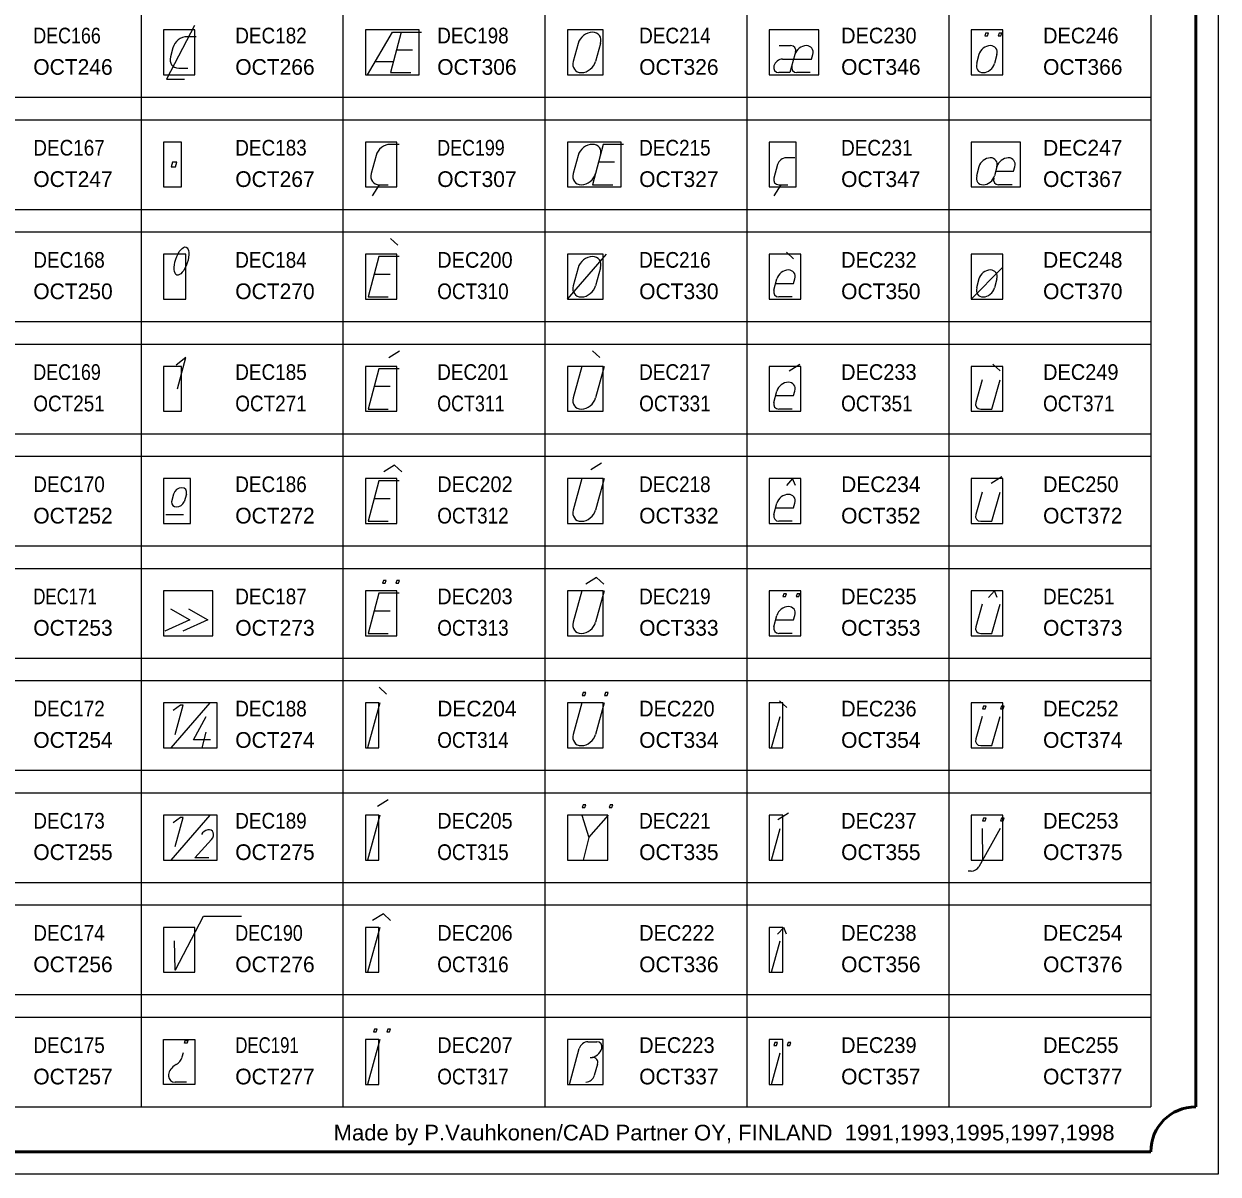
# Model space of a CAD drawing. Extents: x -200 to 7300, y -200 to 4800.
# Drawn here: x 4639 to 7300, y -200 to 2364 of the extents above; entities that cross this region are included whole.
import ezdxf
from ezdxf.enums import TextEntityAlignment as Align

# ---------------------------------------------------------------- set-up
doc = ezdxf.new("R2010")
doc.units = 0
doc.header["$LTSCALE"] = 14
for name, color, linetype, lineweight in [('1', 7, 'Continuous', 13), ('5', 7, 'Continuous', 40), ('6', 7, 'Continuous', 13), ('63', 7, 'Continuous', 13)]:
    doc.layers.add(name, color=color, linetype=linetype, lineweight=lineweight)
doc.layers.add('10', color=7, linetype='Continuous')
doc.layers.add('11', color=7, linetype='Continuous')

msp = doc.modelspace()

# ---------------------------------------------------------------- linework, layer by layer
at = {"layer": '1'}
for p, q in [((5023, 2335), (5003, 2335)), ((5874, 2320), (5863, 2280)), ((5924, 2320), (5913, 2280)), ((4971, 2310), (4966, 2290)), ((5505, 2305), (5470, 2305)), ((6322, 2315), (6347, 2315)), ((6767, 2295), (6762, 2275)), ((6807, 2295), (6802, 2275)), ((4983.9, 2265), (5004, 2265)), ((5422, 2280), (5463, 2280)), ((6391, 2255), (6361, 2255)), ((5475, 2095), (5455, 2095)), ((5424, 2070), (5413, 2030)), ((5874, 2070), (5863, 2030)), ((5955, 2055), (5920, 2055)), ((6318, 2050), (6310, 2020)), ((6357, 2065), (6337, 2065)), ((6767, 2045), (6762, 2025)), ((6807, 2045), (6802, 2025)), ((5431, 2005), (5415, 1980)), ((5431, 2005), (5451, 2005)), ((6326, 2005), (6310, 1980)), ((6321, 2005), (6341, 2005)), ((6841, 2005), (6811, 2005)), ((5472, 1870), (5456, 1885)), ((5850, 1750), (5937, 1850)), ((6354, 1840), (6338, 1855)), ((5874, 1820), (5863, 1780)), ((5924, 1820), (5913, 1780)), ((6819, 1820), (6750, 1750)), ((5455, 1805), (5420, 1805)), ((6310, 1770), (6317, 1795)), ((6767, 1795), (6762, 1775)), ((6807, 1795), (6802, 1775)), ((6351, 1755), (6321, 1755)), ((5452, 1620), (5476, 1635)), ((5922, 1620), (5906, 1635)), ((5882, 1600), (5863, 1530)), ((5932, 1600), (5913, 1530)), ((6344, 1590), (6368, 1605)), ((6814, 1590), (6798, 1605)), ((6774, 1570), (6760, 1520)), ((5455, 1555), (5420, 1555)), ((6310, 1520), (6317, 1545)), ((6351, 1505), (6321, 1505)), ((5902, 1370), (5926, 1385)), ((5882, 1350), (5863, 1280)), ((5932, 1350), (5913, 1280)), ((6794, 1340), (6818, 1355)), ((4972.5, 1315.4), (4968.2, 1298.2)), ((5001.1, 1315.4), (4996.3, 1298.5)), ((5455, 1305), (5420, 1305)), ((6774, 1320), (6760, 1270)), ((6310, 1270), (6317, 1295)), ((4955, 1270), (4995, 1270)), ((6351, 1255), (6321, 1255)), ((5882, 1100), (5863, 1030)), ((5932, 1100), (5913, 1030)), ((6774, 1070), (6760, 1020)), ((5455, 1055), (5420, 1055)), ((6310, 1020), (6317, 1045)), ((6351, 1005), (6321, 1005)), ((5447, 870), (5431, 885)), ((6339, 840), (6323, 855)), ((4967, 750), (5054, 850)), ((5432, 850), (5405, 750)), ((5882, 850), (5863, 780)), ((5932, 850), (5913, 780)), ((6305, 750), (6324, 820)), ((6774, 820), (6760, 770)), ((5036, 750), (5045, 785)), ((5427, 620), (5451, 635)), ((4967, 500), (5054, 600)), ((5432, 600), (5405, 500)), ((6319, 590), (6343, 605)), ((6305, 500), (6324, 570)), ((6814, 570), (6767, 485)), ((6774, 570), (6775, 500)), ((5898, 550), (5885, 500)), ((6750, 475), (6743, 475)), ((5432, 350), (5405, 250)), ((6305, 250), (6324, 320)), ((5432, 100), (5405, 0)), ((5855, 0), (5876.5, 80)), ((5895.5, 95), (5916, 95)), ((4994, 70), (4991, 61)), ((5901.1, 60), (5906.1, 60)), ((6305, 0), (6324, 70)), ((4978, 44), (4974, 41)), ((5917, 45), (5910, 20)), ((5001, 5), (4976, 5))]:
    msp.add_line(p, q, dxfattribs=at)
for points in [[(5019, 2360), (4957, 2240), (4997, 2240)], [(5405, 2250), (5460, 2345), (5525, 2345)], [(5480, 2345), (5456, 2255), (5501, 2255)], [(6357, 2295), (6346, 2255), (6321, 2255)], [(6329, 2285), (6394, 2285), (6397, 2295)], [(5975, 2095), (5930, 2095), (5906, 2005), (5951, 2005)], [(6804, 2035), (6844, 2035), (6847, 2045)], [(5475, 1845), (5430, 1845), (5406, 1755), (5451, 1755)], [(6314, 1785), (6354, 1785), (6357, 1795)], [(4981, 1550), (5000, 1620), (4978, 1603)], [(5475, 1595), (5430, 1595), (5406, 1505), (5451, 1505)], [(6771, 1505), (6796, 1505), (6814, 1570)], [(6314, 1535), (6354, 1535), (6357, 1545)], [(5481, 1365), (5465, 1380), (5441, 1365)], [(5475, 1345), (5430, 1345), (5406, 1255), (5451, 1255)], [(6358, 1335), (6352, 1350), (6338, 1335)], [(6771, 1255), (6796, 1255), (6814, 1320)], [(6314, 1285), (6354, 1285), (6357, 1295)], [(5931, 1115), (5915, 1130), (5891, 1115)], [(5475, 1095), (5430, 1095), (5406, 1005), (5451, 1005)], [(6808, 1085), (6802, 1100), (6788, 1085)], [(6771, 1005), (6796, 1005), (6814, 1070)], [(4966, 1060), (5009, 1035), (4953, 1010)], [(5006, 1060), (5049, 1035), (4993, 1010)], [(6314, 1035), (6354, 1035), (6357, 1045)], [(4976, 780), (4994, 845), (4988, 845), (4972, 833)], [(5055, 768), (5017, 768), (5045, 820)], [(6771, 755), (6796, 755), (6814, 820)], [(4976, 530), (4994, 595), (4988, 595), (4972, 583)], [(5882, 600), (5898, 550), (5942, 600)], [(5051, 505), (5020, 505), (5057, 546)], [(4974, 320), (4975, 255), (4977, 255), (5039, 375), (5124, 375)], [(5456, 365), (5440, 380), (5416, 365)], [(6338, 335), (6332, 350), (6318, 335)]]:
    msp.add_lwpolyline(points, dxfattribs=at)
for points in [[(6780, 2337), (6786, 2337), (6788, 2343), (6782, 2343)], [(6810, 2337), (6816, 2337), (6818, 2343), (6812, 2343)], [(4967, 2045), (4977, 2045), (4980, 2055), (4970, 2055)], [(5438, 1117), (5444, 1117), (5446, 1123), (5440, 1123)], [(5468, 1117), (5474, 1117), (5476, 1123), (5470, 1123)], [(6330, 1087), (6336, 1087), (6338, 1093), (6332, 1093)], [(6360, 1087), (6366, 1087), (6368, 1093), (6362, 1093)], [(5883, 867), (5889, 867), (5891, 873), (5885, 873)], [(5933, 867), (5939, 867), (5941, 873), (5935, 873)], [(6775, 837), (6781, 837), (6783, 843), (6777, 843)], [(6815, 837), (6821, 837), (6823, 843), (6817, 843)], [(5883, 617), (5889, 617), (5891, 623), (5885, 623)], [(5943, 617), (5949, 617), (5951, 623), (5945, 623)], [(6775, 587), (6781, 587), (6783, 593), (6777, 593)], [(6815, 587), (6821, 587), (6823, 593), (6817, 593)], [(5418, 117), (5424, 117), (5426, 123), (5420, 123)], [(5448, 117), (5454, 117), (5456, 123), (5450, 123)], [(5003, 92), (4997, 92), (4998, 98), (5004, 98)], [(6310, 87), (6316, 87), (6318, 93), (6312, 93)], [(6340, 87), (6346, 87), (6348, 93), (6342, 93)]]:
    msp.add_lwpolyline(points, close=True, dxfattribs=at)
for centre, major_axis, start_param, end_param in [((5899, 2320), (-21.5, -18.81), 2.2896326, 5.4312252), ((4995.99, 2310), (-21.5, -18.81), 3.860429, 5.4312252), ((4990.63, 2290), (21.5, 18.81), 2.2896328, 3.860429), ((6343.32, 2300), (-12.9, -11.29), 2.2896327, 3.860429), ((6376.98, 2295), (-17.2, -15.05), 2.2896326, 5.4312252), ((6787, 2295), (-17.2, -15.05), 2.2896326, 5.4312252), ((5888, 2280), (21.5, 18.81), 2.2896328, 5.4312254), ((6325.28, 2270), (-12.9, -11.29), 3.860429, 7.0020216), ((6365.29, 2270), (12.9, 11.29), 2.2896328, 3.860429), ((6782, 2275), (17.2, 15.05), 2.2896328, 5.4312254), ((5448.69, 2070), (-21.5, -18.81), 3.860429, 5.4312252), ((5899, 2070), (-21.5, -18.81), 2.2896326, 5.4312252), ((6333.34, 2050), (-12.9, -11.29), 3.860429, 5.4312252), ((6787, 2045), (-17.2, -15.05), 2.2896326, 5.4312252), ((6827, 2045), (-17.2, -15.05), 2.2896326, 5.4312252), ((5437.97, 2030), (21.5, 18.81), 2.2896328, 3.860429), ((5888, 2030), (21.5, 18.81), 2.2896328, 5.4312254), ((6782, 2025), (17.2, 15.05), 2.2896328, 5.4312254), ((6325.3, 2020), (12.9, 11.29), 2.2896328, 3.860429), ((6815.02, 2020), (12.9, 11.29), 2.2896328, 3.860429), ((5899, 1820), (-21.5, -18.81), 2.2896326, 5.4312252), ((6337.02, 1795), (-17.2, -15.05), 2.2896326, 5.4312252), ((6787, 1795), (-17.2, -15.05), 2.2896326, 5.4312252), ((5888, 1780), (21.5, 18.81), 2.2896328, 5.4312254), ((6325.32, 1770), (12.9, 11.29), 2.2896328, 3.860429), ((6782, 1775), (17.2, 15.05), 2.2896328, 5.4312254), ((6337.03, 1545), (-17.2, -15.05), 2.2896326, 5.4312252), ((5888, 1530), (21.5, 18.81), 2.2896328, 5.4312254), ((6325.33, 1520), (12.9, 11.29), 2.2896328, 3.860429), ((6775, 1520), (12.9, 11.29), 2.2896328, 3.860429), ((4986.79, 1315.43), (-12.29, -10.75), 2.2896326, 5.4312252), ((6337.05, 1295), (-17.2, -15.05), 2.2896326, 5.4312252), ((4982.96, 1301.14), (12.29, 10.75), 2.4993147, 5.2422622), ((5888, 1280), (21.5, 18.81), 2.2896328, 5.4312254), ((6325.35, 1270), (12.9, 11.29), 2.2896328, 3.860429), ((6775, 1270), (12.9, 11.29), 2.2896328, 3.860429), ((6337.06, 1045), (-17.2, -15.05), 2.2896326, 5.4312252), ((5888, 1030), (21.5, 18.81), 2.2896328, 5.4312254), ((6325.36, 1020), (12.9, 11.29), 2.2896328, 3.860429), ((6775, 1020), (12.9, 11.29), 2.2896328, 3.860429), ((5888, 780), (21.5, 18.81), 2.2896328, 5.4312254), ((6775, 770), (12.9, 11.29), 2.2896328, 3.860429), ((5047.28, 553.61), (-12.04, -10.54), 1.7153279, 5.1862467), ((6754.5, 490.48), (12.9, 11.29), 3.8604291, 5.0573215), ((5891.5, 80), (-12.9, -11.29), 3.860429, 5.4312252), ((5906.5, 80), (17.2, 15.05), 3.860429, 5.4312252), ((5911.5, 80), (-12.9, -11.29), 2.2896326, 3.8604289), ((4971.32, 60.7), (17.2, 15.05), 4.4484316, 5.4312253), ((5902.12, 45), (-12.9, -11.29), 2.2896326, 3.8642293), ((4981.75, 25), (17.2, 15.05), 1.3623375, 3.860429), ((5895.42, 20), (-12.9, -11.29), 0.7188363, 2.2896326)]:
    msp.add_ellipse(centre, major_axis=major_axis, ratio=0.765566, start_param=start_param, end_param=end_param, dxfattribs=at)
msp.add_ellipse((4990.22, 1835), major_axis=(10.22, 31.22), ratio=0.408607, dxfattribs=at)
at = {"layer": '5', "lineweight": 53}
for p, q in [((7250, 4650), (7250, -50)), ((7150, -150), (-50, -150))]:
    msp.add_line(p, q, dxfattribs=at)
at = {"layer": '5', "lineweight": 25}
msp.add_lwpolyline([(-200, -200), (-200, 4800), (7300, 4800), (7300, -200)], close=True, dxfattribs=at)
at = {"layer": '5', "lineweight": 53}
msp.add_arc((7250, -150), 100, 90, 179.99999, dxfattribs=at)
at = {"layer": '6'}
for p, q in [((4900, 3950), (4900, -50)), ((5350, 3950), (5350, -50)), ((5800, 3950), (5800, -50)), ((6250, 3950), (6250, -50)), ((6700, 3950), (6700, -50)), ((7150, 3950), (7150, -50)), ((-50, 2200), (7150, 2200)), ((-50, 2150), (7150, 2150)), ((-50, 1950), (7150, 1950)), ((-50, 1900), (7150, 1900)), ((-50, 1700), (7150, 1700)), ((-50, 1650), (7150, 1650)), ((-50, 1450), (7150, 1450)), ((-50, 1400), (7150, 1400)), ((-50, 1200), (7150, 1200)), ((-50, 1150), (7150, 1150)), ((-50, 950), (7150, 950)), ((-50, 900), (7150, 900)), ((-50, 700), (7150, 700)), ((-50, 650), (7150, 650)), ((-50, 450), (7150, 450)), ((-50, 400), (7150, 400)), ((-50, 200), (7150, 200)), ((-50, 150), (7150, 150)), ((-50, -50), (7150, -50))]:
    msp.add_line(p, q, dxfattribs=at)
at = {"layer": '63'}
for points in [[(4950, 2250), (5020, 2250), (5020, 2350), (4950, 2350)], [(5400, 2250), (5520, 2250), (5520, 2350), (5400, 2350)], [(5850, 2250), (5930, 2250), (5930, 2350), (5850, 2350)], [(6300, 2250), (6410, 2250), (6410, 2350), (6300, 2350)], [(6750, 2250), (6820, 2250), (6820, 2350), (6750, 2350)], [(4950, 2000), (4990, 2000), (4990, 2100), (4950, 2100)], [(5400, 2000), (5470, 2000), (5470, 2100), (5400, 2100)], [(5850, 2000), (5970, 2000), (5970, 2100), (5850, 2100)], [(6300, 2000), (6360, 2000), (6360, 2100), (6300, 2100)], [(6750, 2000), (6860, 2000), (6860, 2100), (6750, 2100)], [(4950, 1750), (5000, 1750), (5000, 1850), (4950, 1850)], [(5400, 1750), (5470, 1750), (5470, 1850), (5400, 1850)], [(5850, 1750), (5930, 1750), (5930, 1850), (5850, 1850)], [(6300, 1750), (6370, 1750), (6370, 1850), (6300, 1850)], [(6750, 1750), (6820, 1750), (6820, 1850), (6750, 1850)], [(4950, 1500), (4990, 1500), (4990, 1600), (4950, 1600)], [(5400, 1500), (5470, 1500), (5470, 1600), (5400, 1600)], [(5850, 1500), (5930, 1500), (5930, 1600), (5850, 1600)], [(6300, 1500), (6370, 1500), (6370, 1600), (6300, 1600)], [(6750, 1500), (6820, 1500), (6820, 1600), (6750, 1600)], [(4950, 1250), (5010, 1250), (5010, 1350), (4950, 1350)], [(5400, 1250), (5470, 1250), (5470, 1350), (5400, 1350)], [(5850, 1250), (5930, 1250), (5930, 1350), (5850, 1350)], [(6300, 1250), (6370, 1250), (6370, 1350), (6300, 1350)], [(6750, 1250), (6820, 1250), (6820, 1350), (6750, 1350)], [(4950, 1000), (5060, 1000), (5060, 1100), (4950, 1100)], [(5400, 1000), (5470, 1000), (5470, 1100), (5400, 1100)], [(5850, 1000), (5930, 1000), (5930, 1100), (5850, 1100)], [(6300, 1000), (6370, 1000), (6370, 1100), (6300, 1100)], [(6750, 1000), (6820, 1000), (6820, 1100), (6750, 1100)], [(4950, 750), (5070, 750), (5070, 850), (4950, 850)], [(5400, 750), (5430, 750), (5430, 850), (5400, 850)], [(5850, 750), (5930, 750), (5930, 850), (5850, 850)], [(6300, 750), (6330, 750), (6330, 850), (6300, 850)], [(6750, 750), (6820, 750), (6820, 850), (6750, 850)], [(4950, 500), (5070, 500), (5070, 600), (4950, 600)], [(5400, 500), (5430, 500), (5430, 600), (5400, 600)], [(5850, 500), (5940, 500), (5940, 600), (5850, 600)], [(6300, 500), (6330, 500), (6330, 600), (6300, 600)], [(6750, 500), (6820, 500), (6820, 600), (6750, 600)], [(4950, 250), (5020, 250), (5020, 350), (4950, 350)], [(5400, 250), (5430, 250), (5430, 350), (5400, 350)], [(6300, 250), (6330, 250), (6330, 350), (6300, 350)], [(4950, 100), (5020, 100), (5020, 0), (4950, 0)], [(5400, 0), (5430, 0), (5430, 100), (5400, 100)], [(5850, 0), (5930, 0), (5930, 100), (5850, 100)], [(6300, 0), (6330, 0), (6330, 100), (6300, 100)]]:
    msp.add_lwpolyline(points, close=True, dxfattribs=at)

# ---------------------------------------------------------------- texts
at = {"layer": '10'}
for s, width, p in [('DEC166', 0.85, (4660, 2320)), ('DEC182', 0.9, (5110, 2320)), ('DEC198', 0.9, (5560, 2320)), ('DEC214', 0.9, (6010, 2320)), ('DEC230', 0.95, (6460, 2320)), ('DEC246', 0.95, (6910, 2320)), ('DEC167', 0.9, (4660, 2070)), ('DEC183', 0.9, (5110, 2070)), ('DEC199', 0.85, (5560, 2070)), ('DEC215', 0.9, (6010, 2070)), ('DEC231', 0.9, (6460, 2070)), ('DEC168', 0.9, (4660, 1820)), ('DEC184', 0.9, (5110, 1820)), ('DEC200', 0.95, (5560, 1820)), ('DEC216', 0.9, (6010, 1820)), ('DEC232', 0.95, (6460, 1820)), ('DEC169', 0.85, (4660, 1570)), ('DEC185', 0.9, (5110, 1570)), ('DEC201', 0.9, (5560, 1570)), ('DEC217', 0.9, (6010, 1570)), ('DEC233', 0.95, (6460, 1570)), ('DEC249', 0.95, (6910, 1570)), ('DEC170', 0.9, (4660, 1320)), ('DEC186', 0.9, (5110, 1320)), ('DEC202', 0.95, (5560, 1320)), ('DEC218', 0.9, (6010, 1320)), ('DEC250', 0.95, (6910, 1320)), ('DEC171', 0.8, (4660, 1070)), ('DEC187', 0.9, (5110, 1070)), ('DEC203', 0.95, (5560, 1070)), ('DEC219', 0.9, (6010, 1070)), ('DEC235', 0.95, (6460, 1070)), ('DEC251', 0.9, (6910, 1070)), ('DEC172', 0.9, (4660, 820)), ('DEC188', 0.9, (5110, 820)), ('DEC220', 0.95, (6010, 820)), ('DEC236', 0.95, (6460, 820)), ('DEC252', 0.95, (6910, 820)), ('DEC173', 0.9, (4660, 570)), ('DEC189', 0.9, (5110, 570)), ('DEC205', 0.95, (5560, 570)), ('DEC221', 0.9, (6010, 570)), ('DEC237', 0.95, (6460, 570)), ('DEC253', 0.95, (6910, 570)), ('DEC174', 0.9, (4660, 320)), ('DEC190', 0.85, (5110, 320)), ('DEC206', 0.95, (5560, 320)), ('DEC222', 0.95, (6010, 320)), ('DEC238', 0.95, (6460, 320)), ('DEC175', 0.9, (4660, 70)), ('DEC191', 0.8, (5110, 70)), ('DEC207', 0.95, (5560, 70)), ('DEC223', 0.95, (6010, 70)), ('DEC239', 0.95, (6460, 70)), ('DEC255', 0.95, (6910, 70))]:
    msp.add_text(s, height=35, dxfattribs=dict(at, width=width)).set_placement(p)
for s, p in [('DEC247', (6910, 2070)), ('DEC248', (6910, 1820)), ('DEC234', (6460, 1320)), ('DEC204', (5560, 820)), ('DEC254', (6910, 320))]:
    msp.add_text(s, height=35, dxfattribs=at).set_placement(p)
at = {"layer": '11'}
for s, p in [('OCT246', (4660, 2250)), ('OCT266', (5110, 2250)), ('OCT306', (5560, 2250)), ('OCT326', (6010, 2250)), ('OCT346', (6460, 2250)), ('OCT366', (6910, 2250)), ('OCT247', (4660, 2000)), ('OCT267', (5110, 2000)), ('OCT307', (5560, 2000)), ('OCT327', (6010, 2000)), ('OCT347', (6460, 2000)), ('OCT367', (6910, 2000)), ('OCT250', (4660, 1750)), ('OCT270', (5110, 1750)), ('OCT330', (6010, 1750)), ('OCT350', (6460, 1750)), ('OCT370', (6910, 1750)), ('OCT252', (4660, 1250)), ('OCT272', (5110, 1250)), ('OCT332', (6010, 1250)), ('OCT352', (6460, 1250)), ('OCT372', (6910, 1250)), ('OCT253', (4660, 1000)), ('OCT273', (5110, 1000)), ('OCT333', (6010, 1000)), ('OCT353', (6460, 1000)), ('OCT373', (6910, 1000)), ('OCT254', (4660, 750)), ('OCT274', (5110, 750)), ('OCT334', (6010, 750)), ('OCT354', (6460, 750)), ('OCT374', (6910, 750)), ('OCT255', (4660, 500)), ('OCT275', (5110, 500)), ('OCT335', (6010, 500)), ('OCT355', (6460, 500)), ('OCT375', (6910, 500)), ('OCT256', (4660, 250)), ('OCT276', (5110, 250)), ('OCT336', (6010, 250)), ('OCT356', (6460, 250)), ('OCT376', (6910, 250)), ('OCT257', (4660, 0)), ('OCT277', (5110, 0)), ('OCT337', (6010, 0)), ('OCT357', (6460, 0)), ('OCT377', (6910, 0))]:
    msp.add_text(s, height=35, dxfattribs=at).set_placement(p)
for s, width, p in [('OCT310', 0.9, (5560, 1750)), ('OCT251', 0.9, (4660, 1500)), ('OCT271', 0.9, (5110, 1500)), ('OCT311', 0.85, (5560, 1500)), ('OCT331', 0.9, (6010, 1500)), ('OCT351', 0.9, (6460, 1500)), ('OCT371', 0.9, (6910, 1500)), ('OCT312', 0.9, (5560, 1250)), ('OCT313', 0.9, (5560, 1000)), ('OCT314', 0.9, (5560, 750)), ('OCT315', 0.9, (5560, 500)), ('OCT316', 0.9, (5560, 250)), ('OCT317', 0.9, (5560, 0))]:
    msp.add_text(s, height=35, dxfattribs=dict(at, width=width)).set_placement(p)
at = {"layer": '5', "width": 1.05}
msp.add_text('Made by P.Vauhkonen/CAD Partner OY, FINLAND  1991,1993,1995,1997,1998', height=35, dxfattribs=at).set_placement((7069.3, -125), align=Align.RIGHT)

doc.saveas('drawing.dxf')
